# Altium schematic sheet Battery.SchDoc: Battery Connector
size A4; CheckedBy: Satya Mehta; Organization: Team Ashwathama; Address1: Colorado Boulder; Address2: Author- Satya Mehta; Address3: Self Checkout Shopping Cart; DocumentNumber: 1; Revision: 1.0; SheetNumber: 2; SheetTotal: 7
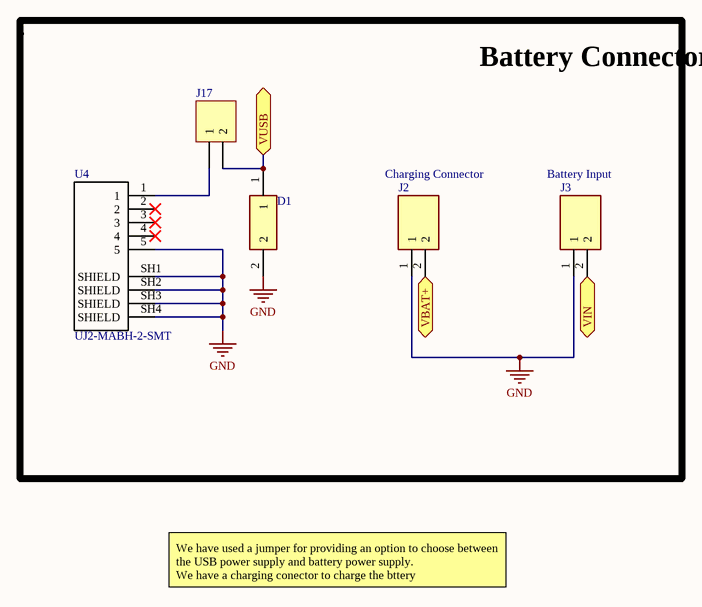
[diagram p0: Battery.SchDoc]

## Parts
D1  TPD1E10B06DPYT  [DPY(R-PX1SON-N2)]  (value not drawn)
J2  282837-2  [SHDR2W100P0X508_1X2_1016X820X1030P]  (value not drawn)
J3  282837-2  [SHDR2W100P0X508_1X2_1016X820X1030P]  (value not drawn)
J17  Header 2  [HDR1X2]  (value not drawn)
U4  UJ2-MABH-2-SMT  [*CUI_UJ2-MABH-2-SMT_UJ2-MABH-2-SMT(Primary)]

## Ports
VBAT+, VIN, VUSB

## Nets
GND: D1.2 J2.1 J3.1 U4.5 U4.SH1(SHIELD) U4.SH2(SHIELD) U4.SH3(SHIELD) U4.SH4(SHIELD)
VBAT+: J2.2 ; port VBAT+
VIN: J3.2 ; port VIN
VUSB: D1.1 J17.2 ; port VUSB
NetJ17_1: J17.1 U4.1

Not connected (* = marked no-connect by the designer): U4 2* 3* 4*

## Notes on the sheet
- Battery Connector
- Charging Connector
- Battery Input
- We have used a jumper for providing an option to choose between the USB power supply and battery power supply.
  We have a charging conector to charge the bttery

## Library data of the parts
D1 = TPD1E10B06DPYT: TVS Diode (Bi-directional); Manufacturer_Name: Texas Instruments
J2 J3 = 282837-2: Connector; Manufacturer_Name: TE Connectivity; Allied_Number: 70086281
J17 = Header 2: Header, 2-Pin; Manufacturer_Part_Number: BG301-04-A-0540-L-B; Manufacturer_Name: Global Connector Technology
U4 = UJ2-MABH-2-SMT: Mini AB, USB 2.0, 1 A, Right Angle, Surface Mount _SMT_, USB Receptacle; Manufacturer_Part_Number: UJ2-MBH-3-SMT-TR; Manufacturer_Name: CUI Inc.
